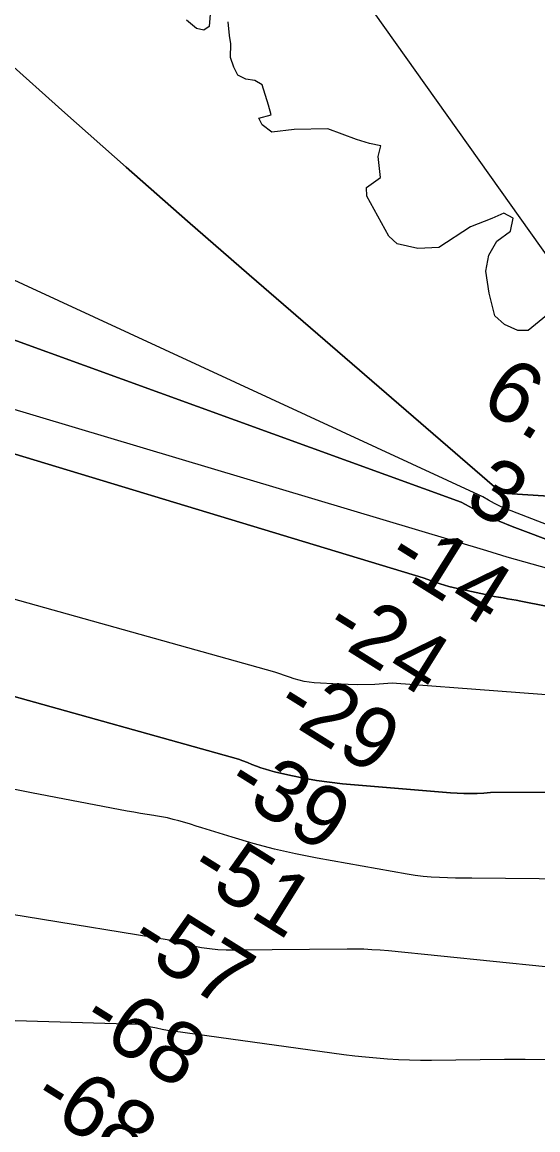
# Model space of a CAD drawing. Extents: x 3279314 to 3317160, y 734079 to 759431.
# Drawn here: x 3287854 to 3288413, y 753859 to 755059 of the extents above; entities that cross this region are included whole.
import ezdxf

# ---------------------------------------------------------------- set-up
doc = ezdxf.new("R2010")
doc.units = 0
for name, color, linetype in [('V-RIVR-EDGE', 7, 'Continuous'), ('V-RIVR-RANG', 7, 'Continuous'), ('V-TOPO-DPTH', 7, 'Continuous'), ('V-TOPO-MAJR', 7, 'Continuous'), ('V-TOPO-MINR', 7, 'Continuous'), ('V-TOPO-WATR', 7, 'Continuous')]:
    doc.layers.add(name, color=color, linetype=linetype)

msp = doc.modelspace()

# ---------------------------------------------------------------- linework, layer by layer
at = {"layer": 'V-RIVR-EDGE'}
for points in [[(3288057.7, 755068), (3288056.4, 755054.5), (3288050.7, 755050.6), (3288042.9, 755052.4), (3288032, 755061.5)], [(3288425.9, 754744.6), (3288402, 754725.1), (3288390.7, 754725.1), (3288376.3, 754731.6), (3288365.9, 754741.2), (3288359.9, 754765.6), (3288356.1, 754789.5), (3288359.6, 754806.9), (3288368.3, 754822.1), (3288383.1, 754832.9), (3288385.8, 754846.8), (3288375.8, 754852.5), (3288362.7, 754846.4), (3288339.7, 754837.4), (3288305.3, 754815.3), (3288282.7, 754814), (3288260.1, 754819.3), (3288251, 754827.6), (3288227.2, 754870.7), (3288226.8, 754880.2), (3288242, 754891.1), (3288239.4, 754913.7), (3288242.5, 754925.4), (3288230.3, 754928), (3288216, 754932), (3288185.2, 754943.8), (3288148.7, 754943), (3288124.3, 754940), (3288113.9, 754947.9), (3288110.4, 754955.3), (3288123.5, 754958.7), (3288120.9, 754969.2), (3288114, 754991.4), (3288105.8, 754996.2), (3288096.2, 754997.5), (3288087.5, 755001.9), (3288083.2, 755010.6), (3288079.7, 755021), (3288079.8, 755035.8), (3288078.5, 755044.9), (3288077.2, 755059.7)]]:
    msp.add_lwpolyline(points, dxfattribs=at)
at = {"layer": 'V-TOPO-DPTH'}
for p, q in [((3287545.4, 754412.4), (3288088.2, 754260.9)), ((3287545.4, 754412.4), (3288088.2, 754260.9)), ((3288088.2, 754260.9), (3288093, 754259)), ((3288088.2, 754260.9), (3288093, 754259)), ((3288093, 754259), (3288097.9, 754257.1)), ((3288093, 754259), (3288097.9, 754257.1)), ((3288097.9, 754257.1), (3288102.7, 754255.2)), ((3288097.9, 754257.1), (3288102.7, 754255.2)), ((3288102.7, 754255.2), (3288107.6, 754253.3)), ((3288102.7, 754255.2), (3288107.6, 754253.3)), ((3288107.6, 754253.3), (3288112.4, 754251.5)), ((3288107.6, 754253.3), (3288112.4, 754251.5)), ((3288112.4, 754251.5), (3288117.4, 754249.9)), ((3288112.4, 754251.5), (3288117.4, 754249.9)), ((3288117.4, 754249.9), (3288122.3, 754248.5)), ((3288117.4, 754249.9), (3288122.3, 754248.5)), ((3288122.3, 754248.5), (3288127.4, 754247.2)), ((3288122.3, 754248.5), (3288127.4, 754247.2)), ((3288127.4, 754247.2), (3288145, 754243.1)), ((3288127.4, 754247.2), (3288145, 754243.1)), ((3288145, 754243.1), (3288158.9, 754240.2)), ((3288145, 754243.1), (3288158.9, 754240.2)), ((3288158.9, 754240.2), (3288172.9, 754237.7)), ((3288158.9, 754240.2), (3288172.9, 754237.7)), ((3288172.9, 754237.7), (3288186.9, 754235.8)), ((3288172.9, 754237.7), (3288186.9, 754235.8)), ((3288186.9, 754235.8), (3288201, 754234.3)), ((3288186.9, 754235.8), (3288201, 754234.3)), ((3288201, 754234.3), (3288317.9, 754224.4)), ((3288201, 754234.3), (3288317.9, 754224.4)), ((3288317.9, 754224.4), (3288325.1, 754223.9)), ((3288317.9, 754224.4), (3288325.1, 754223.9)), ((3288325.1, 754223.9), (3288332.4, 754223.6)), ((3288325.1, 754223.9), (3288332.4, 754223.6)), ((3288332.4, 754223.6), (3288339.6, 754223.6)), ((3288332.4, 754223.6), (3288339.6, 754223.6)), ((3288339.6, 754223.6), (3288346.9, 754223.8)), ((3288339.6, 754223.6), (3288346.9, 754223.8)), ((3288346.9, 754223.8), (3288354.2, 754224.2)), ((3288346.9, 754223.8), (3288354.2, 754224.2)), ((3288354.2, 754224.2), (3288361.4, 754224.8)), ((3288354.2, 754224.2), (3288361.4, 754224.8)), ((3288361.4, 754224.8), (3288795.2, 754226.4)), ((3288361.4, 754224.8), (3288795.2, 754226.4))]:
    msp.add_line(p, q, dxfattribs=at)
for points in [[(3289365.8, 754485.4), (3288373.5, 754549.1), (3288100, 754785.6), (3288033.1, 754843.8), (3287966.5, 754902.2), (3287900.2, 754961.2), (3287834.2, 755020.4)], [(3287834.2, 755020.4), (3287900.2, 754961.2), (3287966.5, 754902.2), (3288033.1, 754843.8), (3288100, 754785.6), (3288373.5, 754549.1), (3289365.8, 754485.4)], [(3287435.3, 754863.6), (3288329.6, 754539.3), (3288343, 754531.9), (3288356.7, 754524.9), (3288370.7, 754518.6), (3288384.9, 754512.8), (3288483.7, 754475.6), (3288496.8, 754471.1), (3288510, 754467.2), (3288523.5, 754464.1), (3288537, 754461.5), (3288550.7, 754459.5), (3288564.4, 754457.5), (3288578.2, 754455.8), (3288591.9, 754454.1), (3289342.2, 754433.1)], [(3287435.3, 754863.6), (3288329.6, 754539.3), (3288343, 754531.9), (3288356.7, 754524.9), (3288370.7, 754518.6), (3288384.9, 754512.8), (3288483.7, 754475.6), (3288496.8, 754471.1), (3288510, 754467.2), (3288523.5, 754464.1), (3288537, 754461.5), (3288550.7, 754459.5), (3288564.4, 754457.5), (3288578.2, 754455.8), (3288591.9, 754454.1), (3289342.2, 754433.1)], [(3288593.4, 754392.6), (3288394, 754432), (3288389.2, 754433), (3288384.5, 754433.8), (3288379.7, 754434.7), (3288374.9, 754435.5), (3288370.1, 754436.3), (3288365.3, 754437.1), (3288360.6, 754438.1), (3288355.8, 754439.1), (3288325.5, 754445.7), (3288316, 754448.1), (3288306.6, 754450.8), (3288297.3, 754453.9), (3288288.2, 754457.4), (3287694.8, 754637.3)], [(3287694.8, 754637.3), (3288288.2, 754457.4), (3288297.3, 754453.9), (3288306.6, 754450.8), (3288316, 754448.1), (3288325.5, 754445.7), (3288355.8, 754439.1), (3288360.6, 754438.1), (3288365.3, 754437.1), (3288370.1, 754436.3), (3288374.9, 754435.5), (3288379.7, 754434.7), (3288384.5, 754433.8), (3288389.2, 754433), (3288394, 754432), (3288593.4, 754392.6)], [(3288712.7, 754308.5), (3288254.9, 754343.1), (3288235.8, 754341.7), (3288216.7, 754341.5), (3288197.5, 754342), (3288170.2, 754343.7), (3288164.7, 754344.2), (3288159.3, 754345), (3288153.9, 754346.3), (3288148.6, 754347.8), (3288143.4, 754349.6), (3288138.1, 754351.4), (3288132.9, 754353.3), (3288127.7, 754355.2), (3287334.7, 754576.9)], [(3288712.7, 754308.5), (3288254.9, 754343.1), (3288235.8, 754341.7), (3288216.7, 754341.5), (3288197.5, 754342), (3288170.2, 754343.7), (3288164.7, 754344.2), (3288159.3, 754345), (3288153.9, 754346.3), (3288148.6, 754347.8), (3288143.4, 754349.6), (3288138.1, 754351.4), (3288132.9, 754353.3), (3288127.7, 754355.2), (3287334.7, 754576.9)]]:
    msp.add_lwpolyline(points, dxfattribs=at)
at = {"layer": 'V-TOPO-MAJR'}
msp.add_lwpolyline([(3288450.4, 754130.7), (3288341.1, 754131.8), (3288332.3, 754132), (3288323.5, 754132.1), (3288314.7, 754132.4), (3288305.9, 754132.6), (3288297.1, 754133.1), (3288288.4, 754133.8), (3288279.7, 754134.9), (3288271, 754136.3), (3288173.4, 754153.7), (3288150.1, 754158.3), (3288127.1, 754163.5), (3288104.2, 754169.6), (3288081.5, 754176.2), (3288048.6, 754186.5), (3288042.4, 754188.4), (3288036.2, 754190.3), (3288030, 754192.1), (3288023.8, 754194), (3288017.5, 754195.6), (3288011.3, 754197.2), (3288004.9, 754198.4), (3287998.5, 754199.5), (3287996.7, 754199.7), (3287989.5, 754200.8), (3287982.2, 754202), (3287974.9, 754203.3), (3287967.6, 754204.6), (3287864.2, 754224.3), (3287828, 754231.6)], dxfattribs=at)
at = {"layer": 'V-TOPO-MINR'}
for p, q in [((3288456, 754758.8), (3287984.7, 755423)), ((3288088.2, 754260.9), (3287545.4, 754412.4)), ((3288093, 754259), (3288088.2, 754260.9)), ((3288097.9, 754257.1), (3288093, 754259)), ((3288102.7, 754255.2), (3288097.9, 754257.1)), ((3288107.6, 754253.3), (3288102.7, 754255.2)), ((3288112.4, 754251.5), (3288107.6, 754253.3)), ((3288117.4, 754249.9), (3288112.4, 754251.5)), ((3288122.3, 754248.5), (3288117.4, 754249.9)), ((3288127.4, 754247.2), (3288122.3, 754248.5)), ((3288145, 754243.1), (3288127.4, 754247.2)), ((3288158.9, 754240.2), (3288145, 754243.1)), ((3288172.9, 754237.7), (3288158.9, 754240.2)), ((3288186.9, 754235.8), (3288172.9, 754237.7)), ((3288201, 754234.3), (3288186.9, 754235.8)), ((3288317.9, 754224.4), (3288201, 754234.3)), ((3288325.1, 754223.9), (3288317.9, 754224.4)), ((3288332.4, 754223.6), (3288325.1, 754223.9)), ((3288339.6, 754223.6), (3288332.4, 754223.6)), ((3288346.9, 754223.8), (3288339.6, 754223.6)), ((3288354.2, 754224.2), (3288346.9, 754223.8)), ((3288361.4, 754224.8), (3288354.2, 754224.2)), ((3288795.2, 754226.4), (3288361.4, 754224.8))]:
    msp.add_line(p, q, dxfattribs=at)
for points in [[(3289350.4, 754478.1), (3288580.1, 754493.4), (3288543, 754496.1), (3288482.7, 754501.9), (3288475.8, 754502.6), (3288468.9, 754503.4), (3288462.1, 754504.3), (3288455.2, 754505.3), (3288448.5, 754506.6), (3288441.7, 754508.2), (3288435.2, 754510.2), (3288428.6, 754512.4), (3288378.9, 754531.6), (3288372.1, 754534.5), (3288365.5, 754537.7), (3288359.2, 754541.3), (3288353, 754545.2), (3287548.8, 754916.7)], [(3289342.2, 754433.1), (3288591.9, 754454.1), (3288578.2, 754455.8), (3288564.4, 754457.5), (3288550.7, 754459.5), (3288537, 754461.5), (3288523.5, 754464.1), (3288510, 754467.2), (3288496.8, 754471.1), (3288483.7, 754475.6), (3288384.9, 754512.8), (3288370.7, 754518.6), (3288356.7, 754524.9), (3288343, 754531.9), (3288329.6, 754539.3), (3287435.3, 754863.6)], [(3289326.5, 754357.6), (3288701.1, 754406), (3288680.5, 754408.7), (3288659.9, 754411.6), (3288639.4, 754414.6), (3288618.8, 754417.8), (3288598.4, 754421.3), (3288578, 754425.4), (3288557.8, 754430.2), (3288537.7, 754435.4), (3288379.4, 754479.7), (3288357.2, 754486.4), (3287423.6, 754765.6)], [(3288593.4, 754392.6), (3288394, 754432), (3288389.2, 754433), (3288384.5, 754433.8), (3288379.7, 754434.7), (3288374.9, 754435.5), (3288370.1, 754436.3), (3288365.3, 754437.1), (3288360.6, 754438.1), (3288355.8, 754439.1), (3288325.5, 754445.7), (3288316, 754448.1), (3288306.6, 754450.8), (3288297.3, 754453.9), (3288288.2, 754457.4), (3287694.8, 754637.3)], [(3288712.7, 754308.5), (3288254.9, 754343.1), (3288235.8, 754341.7), (3288216.7, 754341.5), (3288197.5, 754342), (3288170.2, 754343.7), (3288164.7, 754344.2), (3288159.3, 754345), (3288153.9, 754346.3), (3288148.6, 754347.8), (3288143.4, 754349.6), (3288138.1, 754351.4), (3288132.9, 754353.3), (3288127.7, 754355.2), (3287334.7, 754576.9)], [(3288420.8, 754035.8), (3288250.6, 754053.2), (3288241.7, 754053.9), (3288232.8, 754054.5), (3288223.9, 754055), (3288215, 754055.1), (3288206.1, 754055.2), (3288084, 754053.8), (3288075, 754054), (3288066, 754054.4), (3288057, 754055.3), (3288048.1, 754056.5), (3288039.2, 754058.2), (3288030.4, 754060), (3288021.7, 754062.2), (3288013, 754064.7), (3287548.2, 754140.6)], [(3288421.5, 753935.1), (3288399, 753935.5), (3288376.4, 753935.5), (3288297.4, 753934.6), (3288285.5, 753934.6), (3288273.6, 753934.8), (3288261.7, 753935.3), (3288249.8, 753935.9), (3288237.9, 753936.8), (3288226, 753937.9), (3288214.2, 753939.2), (3288202.4, 753940.7), (3288017.6, 753966.2), (3288011.5, 753967.1), (3288005.5, 753968.1), (3287999.5, 753969.3), (3287993.6, 753970.6), (3287983.4, 753972.9), (3287982.5, 753973), (3287981.6, 753973.2), (3287980.8, 753973.2), (3287979.9, 753973.3), (3287554.7, 753986.2)]]:
    msp.add_lwpolyline(points, dxfattribs=at)
at = {"layer": 'V-TOPO-WATR'}
msp.add_lwpolyline([(3289365.8, 754485.4), (3288373.5, 754549.1), (3288100, 754785.6), (3288033.1, 754843.8), (3287966.5, 754902.2), (3287900.2, 754961.2), (3287834.2, 755020.4)], dxfattribs=at)

# ---------------------------------------------------------------- texts
at = {"layer": 'V-RIVR-RANG'}
for s, p in [('6.9', (3288347.9, 754643.5)), ('3', (3288330.9, 754536.2)), ('-14', (3288245.4, 754471.7)), ('-24', (3288178, 754395.9)), ('-29', (3288124.9, 754311.1)), ('-39', (3288071.4, 754226.7)), ('-51', (3288031.4, 754133.8)), ('-57', (3287966.4, 754056.4)), ('-68', (3287914.7, 753970.8)), ('-68', (3287861.7, 753886.1))]:
    msp.add_text(s, height=67, rotation=327.9886, dxfattribs=at).set_placement(p)

doc.saveas('drawing.dxf')
